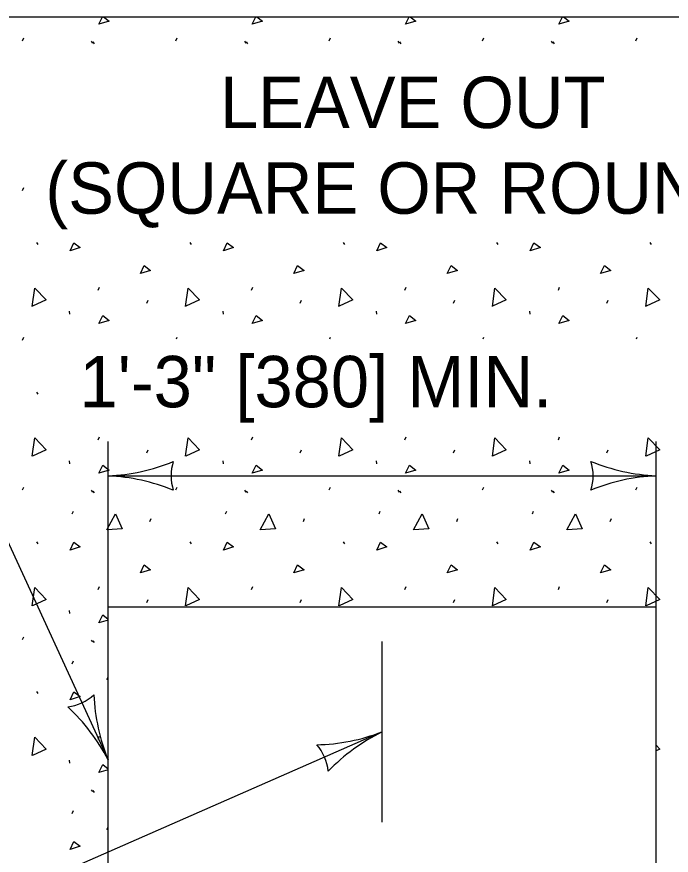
# Model space of a CAD drawing. Extents: x 49991.4 to 50021, y 49987.6 to 50011.4.
# Drawn here: x 50010.444 to 50011.209, y 49996.152 to 49997.131 of the extents above; entities that cross this region are included whole.
import ezdxf

# ---------------------------------------------------------------- set-up
doc = ezdxf.new("R2010")
doc.units = 0
for name, color, linetype in [('Level 1', 7, 'Continuous'), ('Level 2', 7, 'Continuous'), ('Level 3', 7, 'Continuous'), ('Level 5', 7, 'Continuous')]:
    doc.layers.add(name, color=color, linetype=linetype)

msp = doc.modelspace()

# ---------------------------------------------------------------- linework, layer by layer
at = {"layer": 'Level 1'}
for p, q in [((50009.70734, 49997.13065), (50012.03515, 49997.13065)), ((50010.54037, 49997.12196), (50010.54454, 49997.13065)), ((50010.71953, 49997.12196), (50010.7237, 49997.13065)), ((50010.89868, 49997.12196), (50010.90286, 49997.13065)), ((50011.07784, 49997.12196), (50011.08201, 49997.13065)), ((50010.45109, 49997.10257), (50010.45258, 49997.10593)), ((50010.63025, 49997.10257), (50010.63174, 49997.10593)), ((50010.80941, 49997.10257), (50010.8109, 49997.10593)), ((50010.98857, 49997.10257), (50010.99006, 49997.10593)), ((50011.16773, 49997.10257), (50011.16922, 49997.10593)), ((50010.53128, 49997.10207), (50010.53278, 49997.09983)), ((50010.53328, 49997.10122), (50010.53477, 49997.09898)), ((50010.71044, 49997.10207), (50010.71193, 49997.09983)), ((50010.71243, 49997.10122), (50010.71393, 49997.09898)), ((50010.8896, 49997.10207), (50010.89109, 49997.09983)), ((50010.89159, 49997.10122), (50010.89309, 49997.09898)), ((50011.06876, 49997.10207), (50011.07025, 49997.09983)), ((50011.07075, 49997.10122), (50011.07224, 49997.09898)), ((50010.45109, 49996.92785), (50010.45258, 49996.9312)), ((50010.4675, 49996.86725), (50010.46899, 49996.86501)), ((50010.50667, 49996.85756), (50010.51114, 49996.86688)), ((50010.5186, 49996.86129), (50010.50667, 49996.85756)), ((50010.51114, 49996.86688), (50010.5186, 49996.86129)), ((50010.64666, 49996.86725), (50010.64815, 49996.86501)), ((50010.68582, 49996.85756), (50010.6903, 49996.86688)), ((50010.69776, 49996.86129), (50010.68582, 49996.85756)), ((50010.6903, 49996.86688), (50010.69776, 49996.86129)), ((50010.82582, 49996.86725), (50010.82731, 49996.86501)), ((50010.86498, 49996.85756), (50010.86946, 49996.86688)), ((50010.87692, 49996.86129), (50010.86498, 49996.85756)), ((50010.86946, 49996.86688), (50010.87692, 49996.86129)), ((50011.00498, 49996.86725), (50011.00647, 49996.86501)), ((50011.04414, 49996.85756), (50011.04862, 49996.86688)), ((50011.05608, 49996.86129), (50011.04414, 49996.85756)), ((50011.04862, 49996.86688), (50011.05608, 49996.86129)), ((50011.18414, 49996.86725), (50011.18563, 49996.86501)), ((50010.53962, 49996.81168), (50010.54111, 49996.81504)), ((50010.71878, 49996.81168), (50010.72027, 49996.81504)), ((50010.89794, 49996.81168), (50010.89943, 49996.81504)), ((50011.0771, 49996.81168), (50011.07859, 49996.81504)), ((50010.59631, 49996.79639), (50010.5978, 49996.79975)), ((50010.77547, 49996.79639), (50010.77696, 49996.79975)), ((50010.95463, 49996.79639), (50010.95612, 49996.79975)), ((50011.13379, 49996.79639), (50011.13528, 49996.79975)), ((50010.50583, 49996.78702), (50010.5062, 49996.78367)), ((50010.68498, 49996.78702), (50010.68536, 49996.78367)), ((50010.86414, 49996.78702), (50010.86452, 49996.78367)), ((50011.0433, 49996.78702), (50011.04368, 49996.78367)), ((50010.45109, 49996.75313), (50010.45258, 49996.75648)), ((50010.631, 49996.75482), (50010.63174, 49996.75648)), ((50010.81016, 49996.75482), (50010.8109, 49996.75648)), ((50010.98932, 49996.75482), (50010.99006, 49996.75648)), ((50011.16848, 49996.75482), (50011.16922, 49996.75648)), ((50010.4675, 49996.69253), (50010.46899, 49996.69029)), ((50010.53962, 49996.63696), (50010.54111, 49996.64032)), ((50010.71878, 49996.63696), (50010.72027, 49996.64032)), ((50010.89794, 49996.63696), (50010.89943, 49996.64032)), ((50011.0771, 49996.63696), (50011.07859, 49996.64032)), ((50010.59631, 49996.62167), (50010.5978, 49996.62503)), ((50010.77547, 49996.62167), (50010.77696, 49996.62503)), ((50010.95463, 49996.62167), (50010.95612, 49996.62503)), ((50011.13379, 49996.62167), (50011.13528, 49996.62503)), ((50010.50583, 49996.6123), (50010.5062, 49996.60894)), ((50010.68498, 49996.6123), (50010.68536, 49996.60894)), ((50010.86414, 49996.6123), (50010.86452, 49996.60894)), ((50011.0433, 49996.6123), (50011.04368, 49996.60894)), ((50010.45109, 49996.57841), (50010.45258, 49996.58176)), ((50010.53128, 49996.57791), (50010.53278, 49996.57567)), ((50010.53328, 49996.57705), (50010.53477, 49996.57482)), ((50010.63025, 49996.57841), (50010.63174, 49996.58176)), ((50010.71044, 49996.57791), (50010.71193, 49996.57567)), ((50010.71243, 49996.57705), (50010.71393, 49996.57482)), ((50010.80941, 49996.57841), (50010.8109, 49996.58176)), ((50010.8896, 49996.57791), (50010.89109, 49996.57567)), ((50010.89159, 49996.57705), (50010.89309, 49996.57482)), ((50010.98857, 49996.57841), (50010.99006, 49996.58176)), ((50011.06876, 49996.57791), (50011.07025, 49996.57567)), ((50011.07075, 49996.57705), (50011.07224, 49996.57482)), ((50011.16773, 49996.57841), (50011.16922, 49996.58176)), ((50010.50928, 49996.55026), (50010.51077, 49996.55361)), ((50010.68843, 49996.55026), (50010.68993, 49996.55361)), ((50010.86759, 49996.55026), (50010.86908, 49996.55361)), ((50011.04675, 49996.55026), (50011.04824, 49996.55361)), ((50010.60004, 49996.54168), (50010.60153, 49996.54504)), ((50010.7792, 49996.54168), (50010.78069, 49996.54504)), ((50010.95836, 49996.54168), (50010.95985, 49996.54504)), ((50011.13752, 49996.54168), (50011.13901, 49996.54504)), ((50010.4675, 49996.51781), (50010.46899, 49996.51557)), ((50010.50667, 49996.50811), (50010.51114, 49996.51744)), ((50010.51114, 49996.51744), (50010.5186, 49996.51184)), ((50010.64666, 49996.51781), (50010.64815, 49996.51557)), ((50010.68582, 49996.50811), (50010.6903, 49996.51744)), ((50010.6903, 49996.51744), (50010.69776, 49996.51184)), ((50010.82582, 49996.51781), (50010.82731, 49996.51557)), ((50010.86498, 49996.50811), (50010.86946, 49996.51744)), ((50010.86946, 49996.51744), (50010.87692, 49996.51184)), ((50011.00498, 49996.51781), (50011.00647, 49996.51557)), ((50011.04414, 49996.50811), (50011.04862, 49996.51744)), ((50011.04862, 49996.51744), (50011.05608, 49996.51184)), ((50011.18414, 49996.51781), (50011.18563, 49996.51557)), ((50010.5186, 49996.51184), (50010.50667, 49996.50811)), ((50010.69776, 49996.51184), (50010.68582, 49996.50811)), ((50010.87692, 49996.51184), (50010.86498, 49996.50811)), ((50011.05608, 49996.51184), (50011.04414, 49996.50811)), ((50010.53962, 49996.46224), (50010.54111, 49996.4656)), ((50010.71878, 49996.46224), (50010.72027, 49996.4656)), ((50010.89794, 49996.46224), (50010.89943, 49996.4656)), ((50011.0771, 49996.46224), (50011.07859, 49996.4656)), ((50010.59631, 49996.44695), (50010.5978, 49996.4503)), ((50010.77547, 49996.44695), (50010.77696, 49996.4503)), ((50010.95463, 49996.44695), (50010.95612, 49996.4503)), ((50011.13379, 49996.44695), (50011.13528, 49996.4503)), ((50010.55125, 49996.12142), (50010.55125, 49996.44142)), ((50011.19125, 49996.44142), (50010.55125, 49996.44142)), ((50011.19125, 49996.12142), (50011.19125, 49996.44142)), ((50010.50583, 49996.43758), (50010.5062, 49996.43422)), ((50010.55125, 49996.42648), (50010.54037, 49996.42308)), ((50010.45109, 49996.40368), (50010.45258, 49996.40704)), ((50010.53128, 49996.40318), (50010.53278, 49996.40095)), ((50010.53328, 49996.40233), (50010.53477, 49996.4001)), ((50010.50928, 49996.37554), (50010.51077, 49996.37889)), ((50010.54969, 49996.35689), (50010.55125, 49996.35983)), ((50010.55125, 49996.35699), (50010.55006, 49996.35689)), ((50010.4675, 49996.34309), (50010.46899, 49996.34085)), ((50010.50667, 49996.33339), (50010.51114, 49996.34272)), ((50010.51114, 49996.34272), (50010.5186, 49996.33712)), ((50010.5186, 49996.33712), (50010.50667, 49996.33339)), ((50010.53962, 49996.28752), (50010.54111, 49996.29087)), ((50010.50583, 49996.26286), (50010.5062, 49996.2595)), ((50010.55125, 49996.25176), (50010.54037, 49996.24836)), ((50010.53128, 49996.22846), (50010.53278, 49996.22622)), ((50010.53328, 49996.22761), (50010.53477, 49996.22537)), ((50010.50928, 49996.20081), (50010.51077, 49996.20417)), ((50010.54969, 49996.18217), (50010.55125, 49996.18511)), ((50010.55125, 49996.18227), (50010.55006, 49996.18217)), ((50010.50667, 49996.15867), (50010.51114, 49996.16799)), ((50010.51114, 49996.16799), (50010.5186, 49996.1624)), ((50010.5186, 49996.1624), (50010.50667, 49996.15867))]:
    msp.add_line(p, q, dxfattribs=at)
for points in [[(50010.54569, 49997.13065), (50010.5523, 49997.12569), (50010.54037, 49997.12196)], [(50010.72484, 49997.13065), (50010.73146, 49997.12569), (50010.71953, 49997.12196)], [(50010.904, 49997.13065), (50010.91062, 49997.12569), (50010.89868, 49997.12196)], [(50011.08316, 49997.13065), (50011.08978, 49997.12569), (50011.07784, 49997.12196)], [(50010.58893, 49996.8309), (50010.5934, 49996.84022), (50010.60086, 49996.83463), (50010.58893, 49996.8309)], [(50010.76808, 49996.8309), (50010.77256, 49996.84022), (50010.78002, 49996.83463), (50010.76808, 49996.8309)], [(50010.94724, 49996.8309), (50010.95172, 49996.84022), (50010.95918, 49996.83463), (50010.94724, 49996.8309)], [(50011.1264, 49996.8309), (50011.13088, 49996.84022), (50011.13834, 49996.83463), (50011.1264, 49996.8309)], [(50010.46253, 49996.79253), (50010.46548, 49996.81385), (50010.47884, 49996.80006), (50010.46288, 49996.79266)], [(50010.64169, 49996.79253), (50010.64464, 49996.81385), (50010.658, 49996.80006), (50010.64204, 49996.79266)], [(50010.82084, 49996.79253), (50010.8238, 49996.81385), (50010.83716, 49996.80006), (50010.82119, 49996.79266)], [(50011, 49996.79253), (50011.00296, 49996.81385), (50011.01632, 49996.80006), (50011.00035, 49996.79266)], [(50011.17916, 49996.79253), (50011.18212, 49996.81385), (50011.19547, 49996.80006), (50011.17951, 49996.79266)], [(50010.54037, 49996.77252), (50010.54484, 49996.78184), (50010.5523, 49996.77625), (50010.54037, 49996.77252)], [(50010.71953, 49996.77252), (50010.724, 49996.78184), (50010.73146, 49996.77625), (50010.71953, 49996.77252)], [(50010.89868, 49996.77252), (50010.90316, 49996.78184), (50010.91062, 49996.77625), (50010.89868, 49996.77252)], [(50011.07784, 49996.77252), (50011.08232, 49996.78184), (50011.08978, 49996.77625), (50011.07784, 49996.77252)], [(50010.46253, 49996.61781), (50010.46548, 49996.63913), (50010.47884, 49996.62533), (50010.46288, 49996.61794)], [(50010.64169, 49996.61781), (50010.64464, 49996.63913), (50010.658, 49996.62533), (50010.64204, 49996.61794)], [(50010.82084, 49996.61781), (50010.8238, 49996.63913), (50010.83716, 49996.62533), (50010.82119, 49996.61794)], [(50011, 49996.61781), (50011.00296, 49996.63913), (50011.01632, 49996.62533), (50011.00035, 49996.61794)], [(50011.17916, 49996.61781), (50011.18212, 49996.63913), (50011.19547, 49996.62533), (50011.17951, 49996.61794)], [(50010.54037, 49996.5978), (50010.54484, 49996.60712), (50010.5523, 49996.60153), (50010.54037, 49996.5978)], [(50010.71953, 49996.5978), (50010.724, 49996.60712), (50010.73146, 49996.60153), (50010.71953, 49996.5978)], [(50010.89868, 49996.5978), (50010.90316, 49996.60712), (50010.91062, 49996.60153), (50010.89868, 49996.5978)], [(50011.07784, 49996.5978), (50011.08232, 49996.60712), (50011.08978, 49996.60153), (50011.07784, 49996.5978)], [(50010.54969, 49996.53161), (50010.55976, 49996.55063), (50010.56759, 49996.5331), (50010.55006, 49996.53161)], [(50010.72885, 49996.53161), (50010.73892, 49996.55063), (50010.74675, 49996.5331), (50010.72922, 49996.53161)], [(50010.90801, 49996.53161), (50010.91808, 49996.55063), (50010.92591, 49996.5331), (50010.90838, 49996.53161)], [(50011.08717, 49996.53161), (50011.09724, 49996.55063), (50011.10507, 49996.5331), (50011.08754, 49996.53161)], [(50010.58893, 49996.48145), (50010.5934, 49996.49078), (50010.60086, 49996.48518), (50010.58893, 49996.48145)], [(50010.76808, 49996.48145), (50010.77256, 49996.49078), (50010.78002, 49996.48518), (50010.76808, 49996.48145)], [(50010.94724, 49996.48145), (50010.95172, 49996.49078), (50010.95918, 49996.48518), (50010.94724, 49996.48145)], [(50011.1264, 49996.48145), (50011.13088, 49996.49078), (50011.13834, 49996.48518), (50011.1264, 49996.48145)], [(50010.46253, 49996.44309), (50010.46548, 49996.4644), (50010.47884, 49996.45061), (50010.46288, 49996.44321)], [(50010.64169, 49996.44309), (50010.64464, 49996.4644), (50010.658, 49996.45061), (50010.64204, 49996.44321)], [(50010.82084, 49996.44309), (50010.8238, 49996.4644), (50010.83716, 49996.45061), (50010.82119, 49996.44321)], [(50011, 49996.44309), (50011.00296, 49996.4644), (50011.01632, 49996.45061), (50011.00035, 49996.44321)], [(50011.17916, 49996.44309), (50011.18212, 49996.4644), (50011.19547, 49996.45061), (50011.17951, 49996.44321)], [(50010.54037, 49996.42308), (50010.54484, 49996.4324), (50010.55125, 49996.4276)], [(50010.46253, 49996.26837), (50010.46548, 49996.28968), (50010.47884, 49996.27589), (50010.46288, 49996.26849)], [(50011.19125, 49996.28025), (50011.19547, 49996.27589), (50011.19125, 49996.27393)], [(50010.54037, 49996.24836), (50010.54484, 49996.25768), (50010.55125, 49996.25287)]]:
    msp.add_lwpolyline(points, dxfattribs=at)
at = {"layer": 'Level 3'}
for p, q in [((50010.22893, 49996.96073), (50010.55125, 49996.26314)), ((50010.55125, 49996.40142), (50010.55125, 49996.63482)), ((50011.19125, 49996.40142), (50011.19125, 49996.63482)), ((50010.55125, 49996.59482), (50011.19125, 49996.59482)), ((50010.87127, 49996.29603), (50010.49791, 49996.13231))]:
    msp.add_line(p, q, dxfattribs=at)
for centre, radius, start, end in [((50010.54209, 49996.81695), 0.22232, 272.36048, 292.54399), ((50010.67946, 49996.59482), 0.05477, 162.13882, 197.86118), ((50011.06304, 49996.59482), 0.05477, 342.13882, 17.86118), ((50011.20274, 49996.82753), 0.233, 247.92284, 267.17269), ((50010.53976, 49996.3621), 0.233, 67.92284, 87.17269), ((50011.20041, 49996.37268), 0.22232, 92.36048, 112.54399), ((50010.49747, 49996.37953), 0.05477, 276.9383, 312.66066), ((50010.75674, 49996.348), 0.22232, 182.25549, 202.439), ((50010.34482, 49996.1551), 0.233, 27.62679, 46.87664), ((50010.79045, 49996.50314), 0.22232, 271.13388, 291.31739), ((50010.97525, 49996.08752), 0.233, 116.50518, 135.75503), ((50010.75385, 49996.24454), 0.05477, 5.81669, 41.53905)]:
    msp.add_arc(centre, radius, start, end, dxfattribs=at)
at = {"layer": 'Level 5'}
msp.add_line((50010.87129, 49996.19065), (50010.87126, 49996.40142), dxfattribs=at)

# ---------------------------------------------------------------- texts
at = {"layer": 'Level 2'}
for s, p in [('LEAVE OUT', (50010.68178, 49997.00073)), ('(SQUARE OR ROUND)', (50010.47778, 49996.90073)), ('1\'-3" [380] MIN.', (50010.51774, 49996.67482))]:
    msp.add_text(s, height=0.06, dxfattribs=at).set_placement(p)

doc.saveas('drawing.dxf')
